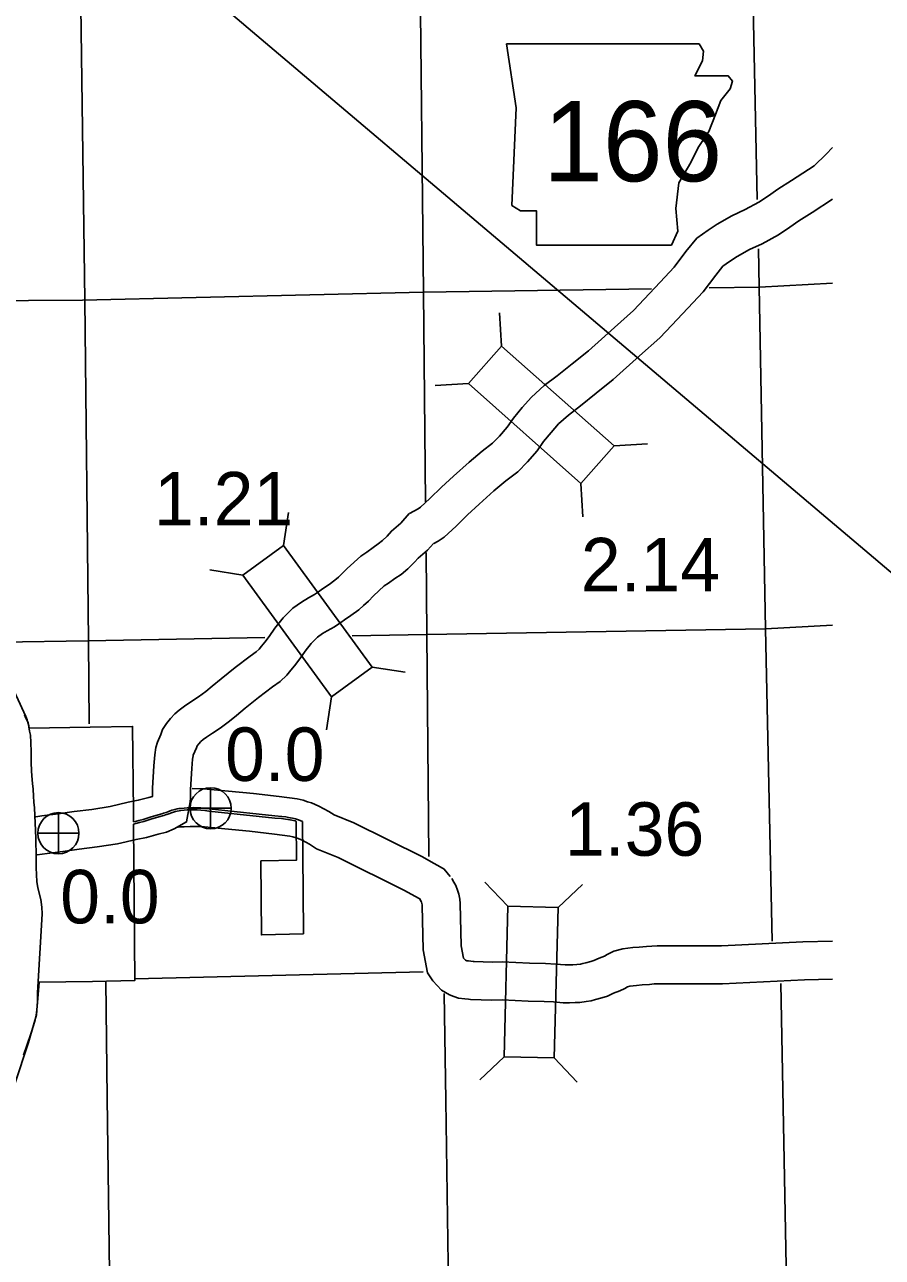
# Model space of a CAD drawing. Extents: x 1369885 to 1370219, y 379980 to 380218.
# Drawn here: x 1369938.61 to 1369960.25, y 380148.46 to 380179.57 of the extents above; entities that cross this region are included whole.
import ezdxf

# ---------------------------------------------------------------- set-up
doc = ezdxf.new("R2010")
doc.units = 0
for name, color, linetype in [('Default', 7, 'Continuous'), ('Level 10', 7, 'Continuous'), ('Level 20', 7, 'Continuous'), ('Level 21', 7, 'Continuous'), ('Level 25', 7, 'Continuous'), ('Level 26', 7, 'Continuous'), ('Level 4', 7, 'Continuous'), ('Level 5', 7, 'Continuous'), ('Level 58', 7, 'Continuous'), ('Level 6', 7, 'Continuous')]:
    doc.layers.add(name, color=color, linetype=linetype)

msp = doc.modelspace()

# ---------------------------------------------------------------- linework, layer by layer
at = {"layer": 'Default'}
msp.add_line((1369969.714, 380157.907), (1369927.244, 380193.89), dxfattribs=at)
at = {"layer": 'Level 10'}
for points in [[(1369958.986, 380176.465), (1369958.829, 380176.294), (1369958.529, 380176.004), (1369957.958, 380175.629), (1369957.613, 380175.413), (1369957.372, 380175.245), (1369957.129, 380175.083), (1369956.785, 380174.897), (1369956.451, 380174.743), (1369956.08, 380174.528), (1369955.857, 380174.38), (1369955.568, 380174.181), (1369955.292, 380173.839), (1369954.992, 380173.443), (1369954.64, 380173.068), (1369954.242, 380172.638), (1369953.971, 380172.355), (1369953.487, 380171.926), (1369952.831, 380171.339), (1369952.422, 380171.006), (1369952.046, 380170.7), (1369951.718, 380170.456), (1369951.395, 380170.164), (1369951.162, 380169.901), (1369950.942, 380169.635), (1369950.779, 380169.405), (1369950.589, 380169.183), (1369950.413, 380169.001), (1369950.153, 380168.8), (1369949.821, 380168.526), (1369949.432, 380168.176), (1369949.123, 380167.891), (1369948.835, 380167.61), (1369948.595, 380167.39), (1369948.54, 380167.352), (1369948.315, 380167.229)], [(1369958.986, 380175.158), (1369958.475, 380174.822), (1369958.142, 380174.614), (1369957.913, 380174.454), (1369957.624, 380174.261), (1369957.214, 380174.039), (1369956.892, 380173.891), (1369956.586, 380173.714), (1369956.395, 380173.587), (1369956.227, 380173.471), (1369956.047, 380173.248), (1369955.726, 380172.824), (1369955.341, 380172.415), (1369954.94, 380171.981), (1369954.636, 380171.663), (1369954.124, 380171.21), (1369953.454, 380170.61), (1369953.027, 380170.263), (1369952.636, 380169.944), (1369952.327, 380169.714), (1369952.077, 380169.489), (1369951.89, 380169.278), (1369951.703, 380169.051), (1369951.535, 380168.815), (1369951.299, 380168.538), (1369951.053, 380168.284), (1369950.751, 380168.051), (1369950.447, 380167.8), (1369950.077, 380167.467), (1369949.783, 380167.195), (1369949.494, 380166.914), (1369949.192, 380166.637), (1369949.041, 380166.534), (1369948.93, 380166.473)], [(1369948.314, 380167.228), (1369948.102, 380166.99), (1369947.864, 380166.787), (1369947.751, 380166.66), (1369947.637, 380166.548), (1369947.532, 380166.461), (1369947.402, 380166.376), (1369947.239, 380166.258), (1369947.087, 380166.155), (1369946.743, 380165.84), (1369946.614, 380165.706), (1369946.525, 380165.625), (1369946.438, 380165.55), (1369946.291, 380165.441), (1369946.126, 380165.332), (1369946.021, 380165.255), (1369945.921, 380165.184), (1369945.768, 380165.102), (1369945.594, 380164.996), (1369945.377, 380164.838), (1369945.131, 380164.594), (1369944.917, 380164.333), (1369944.776, 380164.125), (1369944.666, 380163.98), (1369944.585, 380163.88), (1369944.527, 380163.809), (1369944.451, 380163.738), (1369944.296, 380163.628), (1369943.921, 380163.346), (1369943.565, 380163.061), (1369943.343, 380162.873), (1369943.184, 380162.741), (1369942.995, 380162.601), (1369942.826, 380162.492), (1369942.64, 380162.369), (1369942.511, 380162.268), (1369942.399, 380162.174), (1369942.287, 380162.057), (1369942.187, 380161.935), (1369942.086, 380161.78), (1369942.048, 380161.655), (1369941.962, 380161.463), (1369941.922, 380161.329), (1369941.894, 380161.14), (1369941.871, 380160.864), (1369941.838, 380160.301), (1369941.834, 380160.086), (1369941.742, 380160.064), (1369941.474, 380159.993), (1369941.217, 380159.944), (1369940.768, 380159.837), (1369940.306, 380159.765), (1369939.862, 380159.708), (1369939.451, 380159.655), (1369939.04, 380159.599), (1369938.89, 380159.577)], [(1369948.926, 380166.475), (1369948.773, 380166.303), (1369948.536, 380166.101), (1369948.445, 380165.998), (1369948.28, 380165.837), (1369948.104, 380165.69), (1369947.945, 380165.586), (1369947.788, 380165.473), (1369947.682, 380165.401), (1369947.413, 380165.155), (1369947.282, 380165.018), (1369947.159, 380164.907), (1369947.039, 380164.803), (1369946.842, 380164.656), (1369946.675, 380164.546), (1369946.583, 380164.478), (1369946.425, 380164.367), (1369946.244, 380164.27), (1369946.127, 380164.199), (1369946, 380164.106), (1369945.841, 380163.948), (1369945.685, 380163.759), (1369945.555, 380163.566), (1369945.421, 380163.39), (1369945.328, 380163.274), (1369945.225, 380163.15), (1369945.059, 380162.995), (1369944.863, 380162.855), (1369944.509, 380162.588), (1369944.174, 380162.321), (1369943.958, 380162.137), (1369943.775, 380161.986), (1369943.541, 380161.813), (1369943.352, 380161.691), (1369943.199, 380161.59), (1369943.114, 380161.524), (1369943.056, 380161.474), (1369943.005, 380161.421), (1369942.962, 380161.369), (1369942.947, 380161.319), (1369942.863, 380161.129), (1369942.86, 380161.119), (1369942.846, 380161.03), (1369942.827, 380160.796), (1369942.795, 380160.264), (1369942.792, 380160.052), (1369942.787, 380159.951), (1369942.693, 380159.448), (1369942.384, 380159.275), (1369942.188, 380159.186), (1369941.978, 380159.135), (1369941.686, 380159.058), (1369941.419, 380159.007), (1369940.953, 380158.895), (1369940.44, 380158.816), (1369939.983, 380158.757), (1369939.576, 380158.705), (1369939.175, 380158.651), (1369938.925, 380158.613)], [(1369938.607, 380162.151), (1369938.643, 380162.069), (1369938.65, 380162.049), (1369938.699, 380161.955), (1369938.736, 380161.74), (1369938.753, 380161.64), (1369938.763, 380161.455), (1369938.772, 380161.214), (1369938.773, 380160.948), (1369938.781, 380160.74), (1369938.791, 380160.609), (1369938.811, 380160.418), (1369938.823, 380160.277), (1369938.836, 380160.094), (1369938.845, 380159.947), (1369938.857, 380159.805), (1369938.889, 380159.039), (1369938.9, 380158.551), (1369938.9, 380158.301), (1369938.907, 380158.109), (1369938.916, 380157.943), (1369938.944, 380157.782), (1369939.022, 380157.487), (1369939.043, 380157.3), (1369939.049, 380157.126), (1369938.937, 380155.139), (1369938.932, 380154.92), (1369938.922, 380154.807), (1369938.906, 380154.579), (1369938.851, 380154.379), (1369938.709, 380153.881), (1369937.27, 380149.557)], [(1369949.347, 380158.067), (1369949.193, 380158.257), (1369949.031, 380158.349), (1369948.922, 380158.41), (1369948.644, 380158.567), (1369946.916, 380159.421), (1369946.415, 380159.625), (1369946.282, 380159.71), (1369946.03, 380159.848), (1369945.941, 380159.887), (1369945.845, 380159.926), (1369945.749, 380159.958), (1369945.635, 380159.993), (1369945.484, 380160.031), (1369945.027, 380160.091), (1369944.384, 380160.165), (1369943.75, 380160.223), (1369943.118, 380160.286), (1369942.834, 380160.29)], [(1369948.604, 380157.463), (1369948.564, 380157.512), (1369948.56, 380157.514), (1369948.451, 380157.575), (1369948.195, 380157.72), (1369946.523, 380158.547), (1369945.971, 380158.771), (1369945.792, 380158.886), (1369945.609, 380158.986), (1369945.568, 380159.004), (1369945.512, 380159.027), (1369945.459, 380159.044), (1369945.377, 380159.069), (1369945.302, 380159.088), (1369944.909, 380159.14), (1369944.285, 380159.212), (1369943.659, 380159.269), (1369943.064, 380159.328), (1369942.782, 380159.332), (1369942.634, 380159.324), (1369942.521, 380159.32), (1369942.439, 380159.303)], [(1369958.986, 380156.441), (1369958.243, 380156.419), (1369956.19, 380156.319), (1369954.569, 380156.322), (1369954.428, 380156.314), (1369954.298, 380156.303), (1369954.112, 380156.288), (1369953.949, 380156.276), (1369953.697, 380156.242), (1369953.476, 380156.186), (1369953.307, 380156.099), (1369953.236, 380156.062), (1369953.1, 380156.013), (1369952.968, 380155.95), (1369952.894, 380155.929), (1369952.765, 380155.89), (1369952.695, 380155.873), (1369952.63, 380155.86), (1369952.538, 380155.85), (1369952.442, 380155.844), (1369952.337, 380155.839), (1369952.244, 380155.84), (1369952.014, 380155.862), (1369951.752, 380155.874), (1369951.348, 380155.885), (1369950.66, 380155.913), (1369950.401, 380155.905), (1369949.949, 380155.924), (1369949.925, 380155.928), (1369949.805, 380155.939), (1369949.759, 380155.943), (1369949.749, 380155.947), (1369949.729, 380155.959), (1369949.679, 380156.01), (1369949.622, 380156.319), (1369949.597, 380157.386), (1369949.588, 380157.502), (1369949.559, 380157.628), (1369949.532, 380157.723), (1369949.487, 380157.841), (1369949.438, 380157.927), (1369949.383, 380158.016)], [(1369958.986, 380155.482), (1369958.28, 380155.461), (1369956.213, 380155.361), (1369954.595, 380155.364), (1369954.494, 380155.358), (1369954.376, 380155.348), (1369954.186, 380155.333), (1369954.049, 380155.323), (1369953.881, 380155.3), (1369953.817, 380155.284), (1369953.747, 380155.248), (1369953.623, 380155.183), (1369953.468, 380155.127), (1369953.311, 380155.053), (1369953.169, 380155.01), (1369953.014, 380154.964), (1369952.9, 380154.937), (1369952.774, 380154.912), (1369952.618, 380154.895), (1369952.497, 380154.888), (1369952.354, 380154.88), (1369952.191, 380154.883), (1369951.947, 380154.905), (1369951.716, 380154.917), (1369951.315, 380154.927), (1369950.654, 380154.954), (1369950.396, 380154.947), (1369949.857, 380154.969), (1369949.81, 380154.976), (1369949.718, 380154.984), (1369949.555, 380154.999), (1369949.439, 380155.039), (1369949.324, 380155.084), (1369949.129, 380155.201), (1369948.903, 380155.434), (1369948.773, 380155.64), (1369948.666, 380156.22), (1369948.639, 380157.338), (1369948.638, 380157.357), (1369948.63, 380157.39), (1369948.621, 380157.422), (1369948.618, 380157.431), (1369948.613, 380157.439), (1369948.567, 380157.514)]]:
    msp.add_lwpolyline(points, dxfattribs=at)
at = {"layer": 'Level 20'}
for p, q in [((1369950.643, 380171.454), (1369950.592, 380172.295)), ((1369949.804, 380170.507), (1369948.962, 380170.456)), ((1369953.483, 380168.936), (1369954.324, 380168.987)), ((1369952.643, 380167.989), (1369952.694, 380167.148)), ((1369945.139, 380166.42), (1369945.27, 380167.253)), ((1369944.117, 380165.674), (1369943.284, 380165.805)), ((1369947.375, 380163.353), (1369948.208, 380163.223)), ((1369946.353, 380162.608), (1369946.222, 380161.775)), ((1369950.803, 380157.318), (1369950.223, 380157.929)), ((1369952.068, 380157.285), (1369952.679, 380157.866)), ((1369950.705, 380153.524), (1369950.094, 380152.943)), ((1369951.97, 380153.491), (1369952.551, 380152.88))]:
    msp.add_line(p, q, dxfattribs=at)
for points in [[(1369949.804, 380170.507), (1369952.643, 380167.989), (1369953.483, 380168.936), (1369950.643, 380171.454)], [(1369947.375, 380163.353), (1369945.139, 380166.42), (1369944.117, 380165.674), (1369946.353, 380162.608)], [(1369950.803, 380157.318), (1369950.705, 380153.524), (1369951.97, 380153.491), (1369952.068, 380157.285)]]:
    msp.add_lwpolyline(points, close=True, dxfattribs=at)
at = {"layer": 'Level 21'}
msp.add_lwpolyline([(1369950.764, 380179.084), (1369951.008, 380177.463), (1369950.899, 380175.004), (1369951.116, 380174.869), (1369951.521, 380174.869), (1369951.521, 380174.004), (1369954.926, 380174.004), (1369955.088, 380174.355), (1369955.034, 380174.923), (1369955.115, 380175.571), (1369955.412, 380176.085), (1369955.601, 380176.463), (1369955.871, 380176.868), (1369956.034, 380177.301), (1369956.169, 380177.652), (1369956.412, 380177.949), (1369956.466, 380178.139), (1369956.358, 380178.274), (1369955.52, 380178.274), (1369955.709, 380178.652), (1369955.736, 380178.895), (1369955.624, 380179.082)], close=True, dxfattribs=at)
at = {"layer": 'Level 26'}
for p, q in [((1369943.301, 380159.273), (1369943.301, 380160.311)), ((1369942.782, 380159.792), (1369943.82, 380159.792)), ((1369939.461, 380158.644), (1369939.461, 380159.682)), ((1369938.942, 380159.163), (1369939.98, 380159.163))]:
    msp.add_line(p, q, dxfattribs=at)
for centre in [(1369943.301, 380159.792), (1369939.461, 380159.163)]:
    msp.add_circle(centre, 0.519, dxfattribs=at)
at = {"layer": 'Level 4'}
msp.add_lwpolyline([(1369948.659, 380155.664), (1369941.39, 380155.489)], dxfattribs=at)
at = {"layer": 'Level 5'}
for points in [[(1369957.093, 380175.151), (1369956.953, 380181.666), (1369956.793, 380190.233), (1369956.598, 380198.769), (1369956.602, 380205.77)], [(1369948.189, 380205.291), (1369948.248, 380198.638), (1369948.425, 380190.028), (1369948.583, 380181.454), (1369948.675, 380172.819), (1369948.725, 380167.527)], [(1369940.235, 380161.925), (1369940.222, 380164.017), (1369940.127, 380172.612), (1369940.009, 380181.258), (1369939.946, 380189.836), (1369939.826, 380198.359), (1369939.763, 380204.868)], [(1369957.466, 380156.438), (1369957.296, 380164.316), (1369957.14, 380172.94), (1369957.12, 380173.907)], [(1369948.675, 380172.819), (1369940.069, 380172.615), (1369931.902, 380172.561)], [(1369954.423, 380172.903), (1369948.675, 380172.819)], [(1369958.986, 380173.041), (1369957.15, 380172.944), (1369955.882, 380172.925)], [(1369948.737, 380166.248), (1369948.757, 380164.176), (1369957.296, 380164.316), (1369958.986, 380164.412)], [(1369944.671, 380164.098), (1369940.216, 380164.013), (1369938, 380163.984)], [(1369948.757, 380164.176), (1369946.876, 380164.14)], [(1369948.757, 380164.176), (1369948.81, 380158.572)], [(1369940.695, 380152.485), (1369940.657, 380155.43)], [(1369949.195, 380155.122), (1369949.234, 380152.414)], [(1369957.927, 380138.826), (1369957.838, 380147.346), (1369957.682, 380155.37)], [(1369949.234, 380152.414), (1369949.311, 380147.12), (1369949.472, 380138.551), (1369940.922, 380138.331), (1369932.672, 380138.177)], [(1369940.922, 380138.331), (1369940.769, 380146.823), (1369940.695, 380152.485)]]:
    msp.add_lwpolyline(points, dxfattribs=at)
at = {"layer": 'Level 6'}
for points in [[(1369938.725, 380161.817), (1369938.713, 380161.873), (1369938.689, 380161.96), (1369938.67, 380162.024), (1369938.639, 380162.104), (1369938.59, 380162.219), (1369938.447, 380162.528), (1369938.075, 380163.318), (1369937.688, 380164.174), (1369937.46, 380164.662), (1369937.16, 380165.316), (1369936.836, 380166.021), (1369936.596, 380166.557), (1369936.454, 380166.843), (1369936.348, 380167.074), (1369935.82, 380168.227), (1369935.295, 380168.222)], [(1369941.355, 380159.447), (1369941.352, 380159.722), (1369941.333, 380161.858), (1369940.265, 380161.835), (1369938.725, 380161.817)], [(1369941.355, 380159.392), (1369941.417, 380159.408), (1369941.507, 380159.431), (1369941.614, 380159.462), (1369941.792, 380159.515), (1369941.991, 380159.575), (1369942.086, 380159.603), (1369942.124, 380159.612), (1369942.161, 380159.623), (1369942.199, 380159.635), (1369942.245, 380159.65), (1369942.318, 380159.676), (1369942.366, 380159.692), (1369942.417, 380159.707), (1369942.461, 380159.719), (1369942.508, 380159.73), (1369942.553, 380159.735), (1369942.636, 380159.745), (1369942.711, 380159.75), (1369942.791, 380159.754), (1369942.875, 380159.756), (1369942.96, 380159.753), (1369943.051, 380159.748), (1369943.157, 380159.736), (1369943.26, 380159.723), (1369944.524, 380159.583), (1369944.918, 380159.546), (1369945.089, 380159.533), (1369945.189, 380159.521), (1369945.253, 380159.51), (1369945.302, 380159.501), (1369945.353, 380159.49), (1369945.393, 380159.481), (1369945.431, 380159.471), (1369945.459, 380159.462), (1369945.468, 380158.485), (1369944.568, 380158.463), (1369944.584, 380156.598), (1369945.644, 380156.625), (1369945.634, 380157.69), (1369945.619, 380159.457), (1369945.561, 380159.481), (1369945.496, 380159.506), (1369945.446, 380159.522), (1369945.406, 380159.533), (1369945.364, 380159.542), (1369945.312, 380159.553), (1369945.263, 380159.562), (1369945.196, 380159.573), (1369945.095, 380159.585), (1369944.92, 380159.603), (1369944.526, 380159.641), (1369943.264, 380159.779), (1369943.166, 380159.79), (1369943.055, 380159.801), (1369942.962, 380159.806), (1369942.876, 380159.809), (1369942.789, 380159.807), (1369942.708, 380159.803), (1369942.632, 380159.798), (1369942.545, 380159.79), (1369942.499, 380159.784), (1369942.456, 380159.777), (1369942.396, 380159.763), (1369942.368, 380159.755), (1369942.322, 380159.74), (1369942.218, 380159.701), (1369942.178, 380159.687), (1369942.145, 380159.676), (1369942.11, 380159.665), (1369942.071, 380159.653), (1369941.976, 380159.625), (1369941.777, 380159.566), (1369941.599, 380159.512), (1369941.494, 380159.483), (1369941.404, 380159.46), (1369941.355, 380159.447)], [(1369938.579, 380153.559), (1369938.755, 380154.074), (1369938.833, 380154.307), (1369938.874, 380154.454), (1369938.9, 380154.569), (1369938.918, 380154.709), (1369938.928, 380154.792), (1369938.976, 380155.407), (1369940.322, 380155.422), (1369941.39, 380155.45), (1369941.355, 380159.392)]]:
    msp.add_lwpolyline(points, dxfattribs=at)

# ---------------------------------------------------------------- texts
at = {"layer": 'Level 21'}
msp.add_text('166', height=2.024, dxfattribs=at).set_placement((1369951.692, 380175.612))
at = {"layer": 'Level 25'}
for p in [(1369943.665, 380160.482), (1369939.507, 380156.888)]:
    msp.add_text('0.0', height=1.3493, dxfattribs=at).set_placement(p)
at = {"layer": 'Level 58'}
for s, p in [('1.21', (1369941.873, 380166.929)), ('2.14', (1369952.642, 380165.265)), ('1.36', (1369952.242, 380158.594))]:
    msp.add_text(s, height=1.3493, dxfattribs=at).set_placement(p)

doc.saveas('drawing.dxf')
